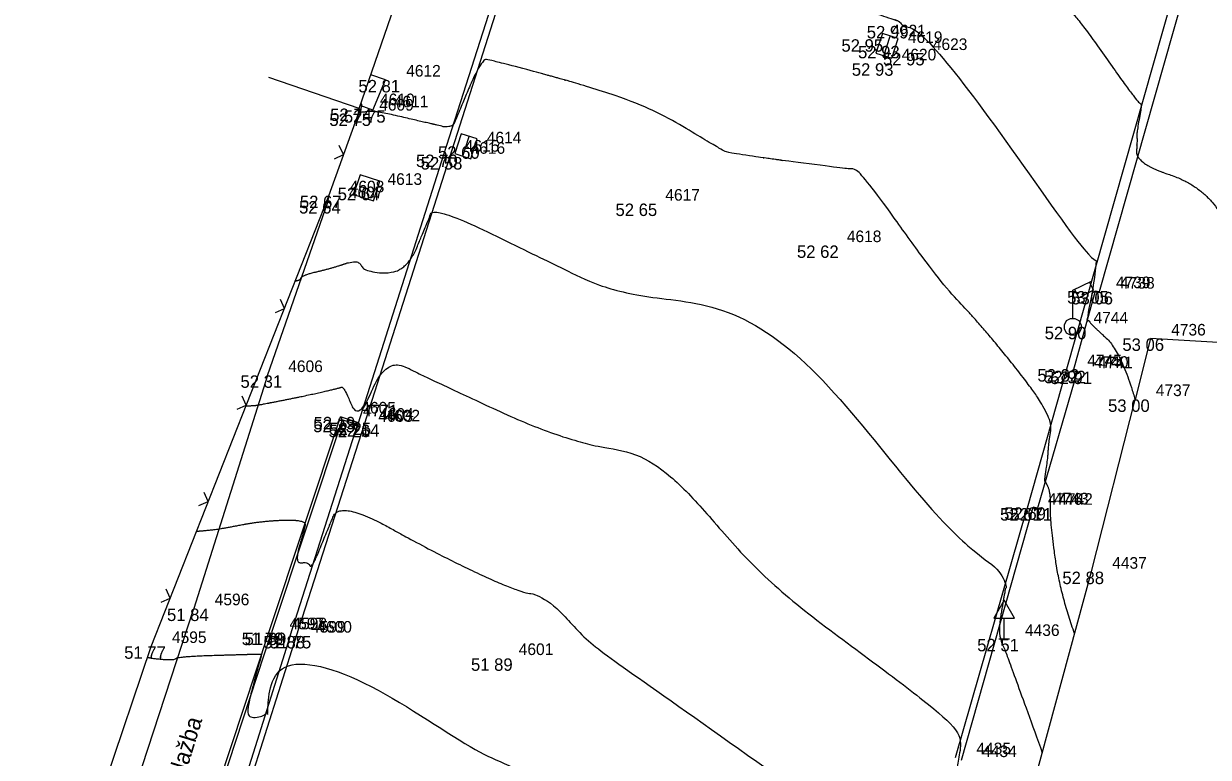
# Model space of a CAD drawing. Extents: x -704017 to -701500, y -1008977 to -1008450.
# Drawn here: x -701728.02 to -701699.5, y -1008889.61 to -1008871.93 of the extents above; entities that cross this region are included whole.
import ezdxf

# ---------------------------------------------------------------- set-up
doc = ezdxf.new("R2010")
doc.units = 0
for name, color, linetype in [('Z_bet_konstrukce', 7, 'Continuous'), ('Z_body', 7, 'Continuous'), ('Z_body_cisla', 7, 'Continuous'), ('Z_body_vysky', 7, 'Continuous'), ('Z_budovy', 7, 'Continuous'), ('Z_chodnik', 7, 'Continuous'), ('Z_dopravni_znaceni', 7, 'Continuous'), ('Z_komunikace', 7, 'Continuous'), ('Z_obruby', 7, 'Continuous'), ('Z_oploceni', 7, 'Continuous'), ('Z_popis', 7, 'Continuous'), ('Z_site_znaky_kanalizace', 7, 'Continuous'), ('Z_site_znaky_nerozlisene', 7, 'Continuous'), ('Z_site_znaky_VO', 7, 'Continuous'), ('Z_vrstevnice_hlavni', 7, 'Continuous'), ('Z_vrstevnice_vedlejsi', 7, 'Continuous'), ('Z_vstupy', 7, 'Continuous')]:
    doc.layers.add(name, color=color, linetype=linetype)

# ---------------------------------------------------------------- blocks, each defined once
blk = doc.blocks.new('POINT_DISPLAY')
blk.add_line((0, 0), (0, 0))
blk = doc.blocks.new('Z212')
for p, q in [((-0.17, 0.17), (0, 0)), ((0, 0), (0.17, 0.17))]:
    blk.add_line(p, q)
blk = doc.blocks.new('Z13')
for p, q in [((0, 0.88), (0.45, 1.1)), ((0, 0.2), (0, 0.88)), ((0.15, 0.7), (0.05, 0.9)), ((0.5, 0.88), (0.15, 0.7)), ((0.4, 1.07), (0.5, 0.88)), ((-0.2, 0.05), (-0.15, 0.15)), ((-0.2, -0.05), (-0.2, 0.05)), ((-0.15, 0.15), (-0.05, 0.2)), ((-0.05, 0.2), (0.05, 0.2)), ((0.05, 0.2), (0.15, 0.15)), ((0.15, 0.15), (0.2, 0.05)), ((0.2, 0.05), (0.2, -0.05)), ((-0.15, -0.15), (-0.2, -0.05)), ((-0.05, -0.2), (-0.15, -0.15)), ((0.05, -0.2), (-0.05, -0.2)), ((0.15, -0.15), (0.05, -0.2)), ((0.2, -0.05), (0.15, -0.15))]:
    blk.add_line(p, q)
blk = doc.blocks.new('Z527')
for p, q in [((0, 0.93), (-0.25, 0.5)), ((0.25, 0.5), (0, 0.93)), ((-0.25, 0.5), (0.25, 0.5)), ((0, 0), (0, 0.5)), ((-0.13, 0), (0.13, 0))]:
    blk.add_line(p, q)
blk = doc.blocks.new('Z38')
for p, q in [((0.25, 0.2), (-0.25, 0.2)), ((-0.25, 0.2), (-0.25, -0.2)), ((-0.25, 0), (0.25, 0)), ((0.25, -0.2), (0.25, 0.2)), ((-0.25, -0.2), (0.25, -0.2))]:
    blk.add_line(p, q)
blk = doc.blocks.new('Z608')
for p, q in [((0.25, 0.25), (-0.25, 0.25)), ((-0.25, 0.25), (-0.25, -0.25)), ((0.25, -0.25), (0.25, 0.25)), ((-0.25, -0.25), (0.25, -0.25))]:
    blk.add_line(p, q)

msp = doc.modelspace()

# ---------------------------------------------------------------- linework, layer by layer
at = {"layer": 'Z_bet_konstrukce'}
for p, q in [((-701719.31, -1008873.29), (-701719.66, -1008873.17)), ((-701719.61, -1008874.02), (-701719.31, -1008873.29)), ((-701719.61, -1008874.02), (-701719.92, -1008873.91))]:
    msp.add_line(p, q, dxfattribs=at)
at = {"layer": 'Z_budovy'}
for p, q in [((-701719.94, -1008873.98), (-701718.32, -1008869.25)), ((-701719.94, -1008873.98), (-701722.12, -1008873.23)), ((-701700.89, -1008879.52), (-701701.26, -1008880.99)), ((-701698.79, -1008879.65), (-701700.89, -1008879.52)), ((-701704.24, -1008892.26), (-701702.31, -1008885.14))]:
    msp.add_line(p, q, dxfattribs=at)
at = {"layer": 'Z_chodnik'}
for p, q in [((-701720.69, -1008876.21), (-701720.67, -1008876.08)), ((-701722.15, -1008880.41), (-701720.69, -1008876.21)), ((-701722.15, -1008880.41), (-701723.92, -1008886.03)), ((-701722.12, -1008886.61), (-701720.39, -1008881.41)), ((-701719.96, -1008881.55), (-701720.39, -1008881.41)), ((-701726.77, -1008894.73), (-701723.92, -1008886.03)), ((-701725.43, -1008896.65), (-701722.12, -1008886.61))]:
    msp.add_line(p, q, dxfattribs=at)
at = {"layer": 'Z_komunikace'}
for p, q in [((-701717.76, -1008875.15), (-701713.25, -1008861.01)), ((-701700.24, -1008870.85), (-701702.91, -1008880.26)), ((-701719.81, -1008881.59), (-701717.76, -1008875.15)), ((-701702.91, -1008880.26), (-701703.86, -1008883.61)), ((-701721.45, -1008886.69), (-701719.81, -1008881.59)), ((-701705.58, -1008889.62), (-701703.86, -1008883.61)), ((-701724.69, -1008896.86), (-701721.45, -1008886.69))]:
    msp.add_line(p, q, dxfattribs=at)
at = {"layer": 'Z_obruby'}
for p, q in [((-701717.9, -1008875.09), (-701713.07, -1008859.91)), ((-701700, -1008870.9), (-701702.12, -1008878.4)), ((-701719.96, -1008881.55), (-701717.9, -1008875.09)), ((-701702.22, -1008878.38), (-701702.75, -1008880.3)), ((-701702.12, -1008878.4), (-701702.22, -1008878.38)), ((-701702.65, -1008880.32), (-701703.61, -1008883.61)), ((-701702.75, -1008880.3), (-701702.65, -1008880.32)), ((-701720.35, -1008881.48), (-701722.05, -1008886.61)), ((-701719.98, -1008881.6), (-701720.35, -1008881.48)), ((-701721.6, -1008886.69), (-701719.98, -1008881.6)), ((-701719.98, -1008881.6), (-701719.96, -1008881.55)), ((-701705.44, -1008889.68), (-701703.71, -1008883.59)), ((-701703.61, -1008883.61), (-701703.71, -1008883.59)), ((-701725.35, -1008896.63), (-701722.05, -1008886.61)), ((-701721.6, -1008886.69), (-701724.81, -1008896.8))]:
    msp.add_line(p, q, dxfattribs=at)
at = {"layer": 'Z_oploceni'}
for p, q in [((-701720.67, -1008876.08), (-701719.96, -1008874.1)), ((-701719.96, -1008874.1), (-701719.94, -1008873.98)), ((-701724.95, -1008886.94), (-701720.67, -1008876.08)), ((-701728.02, -1008896.03), (-701724.95, -1008886.94))]:
    msp.add_line(p, q, dxfattribs=at)
at = {"layer": 'Z_vrstevnice_hlavni'}
for points in [[(-701718.86, -1008870.827), (-701718.722, -1008870.891), (-701718.66, -1008870.875), (-701718.15, -1008870.99), (-701717.866, -1008871.139), (-701716.583, -1008870.95), (-701716.35, -1008870.397), (-701715.903, -1008869.328), (-701715.722, -1008869.338), (-701708.062, -1008871.441), (-701707.666, -1008871.622), (-701707.036, -1008871.849), (-701706.979, -1008871.856), (-701706.917, -1008871.902), (-701706.873, -1008871.965), (-701705.991, -1008872.461), (-701702.302, -1008877.715), (-701702.147, -1008877.571), (-701702.37, -1008878.789), (-701702.424, -1008879.118), (-701702.374, -1008879.073), (-701702.332, -1008879.168), (-701701.594, -1008879.84), (-701701.26, -1008880.99)], [(-701723.856, -1008884.165), (-701723.757, -1008884.159), (-701723.317, -1008884.117), (-701722.306, -1008883.918), (-701721.212, -1008883.88), (-701721.275, -1008884.162), (-701721.5, -1008884.95), (-701721.171, -1008884.904), (-701721.088, -1008885.083), (-701720.729, -1008884.195), (-701720.399, -1008883.421), (-701718.012, -1008884.748), (-701716.089, -1008885.644), (-701715.41, -1008885.731), (-701714.654, -1008886.677), (-701712.69, -1008888.078), (-701706.725, -1008892.293), (-701706.411, -1008892.551), (-701706.575, -1008893.458), (-701706.696, -1008894.086), (-701705.776, -1008894.749), (-701705.243, -1008895.044), (-701705.017, -1008895.187)]]:
    msp.add_open_spline(points, degree=2, dxfattribs=at)
at = {"layer": 'Z_vrstevnice_vedlejsi'}
for points in [[(-701717.871, -1008867.857), (-701717.756, -1008867.838), (-701717.673, -1008867.822), (-701715.485, -1008867.5), (-701715.058, -1008866.486), (-701714.798, -1008865.862), (-701714.692, -1008865.868), (-701710.224, -1008867.095), (-701707.844, -1008868.181), (-701707.424, -1008868.333), (-701705.961, -1008868.506), (-701704.335, -1008869.709), (-701703.188, -1008871.346), (-701702.796, -1008871.566), (-701701.156, -1008873.901), (-701701.088, -1008873.837), (-701701.23, -1008874.615), (-701701.204, -1008874.722), (-701701.244, -1008875.302), (-701699.632, -1008875.838), (-701698.821, -1008877.113), (-701698.653, -1008877.266), (-701698.355, -1008877.477)], [(-701702.715, -1008886.633), (-701703.048, -1008885.709), (-701703.304, -1008883.97), (-701703.286, -1008883.249), (-701703.418, -1008882.952), (-701703.446, -1008882.98), (-701703.355, -1008882.392), (-701703.341, -1008882.053), (-701703.227, -1008881.377), (-701704.937, -1008879.217), (-701705.942, -1008878.19), (-701707.885, -1008875.452), (-701708.146, -1008875.439), (-701711.038, -1008875.063), (-701711.257, -1008874.95), (-701713.196, -1008873.784), (-701716.752, -1008872.808), (-701717.008, -1008872.793), (-701717.642, -1008874.308), (-701717.68, -1008874.4), (-701717.894, -1008874.432), (-701717.942, -1008874.407), (-701718.541, -1008874.272), (-701719.61, -1008874.02), (-701719.96, -1008874.1), (-701719.85, -1008873.881), (-701719.898, -1008873.859)], [(-701721.478, -1008878.131), (-701721.369, -1008878.125), (-701721.309, -1008877.992), (-701720.597, -1008877.828), (-701719.956, -1008877.607), (-701719.832, -1008877.922), (-701718.816, -1008877.961), (-701718.293, -1008876.702), (-701718.133, -1008876.321), (-701715.052, -1008877.835), (-701713.767, -1008878.433), (-701709.999, -1008878.916), (-701705.806, -1008884.163), (-701704.321, -1008885.222), (-701704.421, -1008885.764), (-701704.553, -1008886.557), (-701704.459, -1008886.899), (-701704.403, -1008886.98), (-701703.493, -1008889.504)], [(-701722.667, -1008881.148), (-701722.461, -1008881.136), (-701722.376, -1008881.127), (-701721.27, -1008880.91), (-701720.43, -1008880.717), (-701720.306, -1008880.674), (-701719.96, -1008881.55), (-701719.298, -1008879.98), (-701718.356, -1008880.443), (-701714.928, -1008882.038), (-701712.704, -1008882.323), (-701710.23, -1008885.42), (-701705.37, -1008888.887), (-701705.51, -1008889.65), (-701705.629, -1008890.31), (-701705.649, -1008890.414), (-701705.452, -1008890.557), (-701705.232, -1008890.611), (-701704.313, -1008892.242), (-701704.798, -1008892.26), (-701704.848, -1008892.438), (-701705.159, -1008894.062), (-701704.751, -1008894.196)], [(-701719.96, -1008881.55), (-701720.103, -1008881.56), (-701720.023, -1008881.734), (-701720.009, -1008881.7), (-701719.966, -1008881.599), (-701719.96, -1008881.55)], [(-701725.036, -1008887.196), (-701725.026, -1008887.22), (-701724.401, -1008887.279), (-701724.297, -1008887.181), (-701722.415, -1008887.126), (-701722.29, -1008887.125), (-701722.307, -1008887.191), (-701722.635, -1008888.386), (-701722.61, -1008888.678), (-701722.214, -1008888.623), (-701722.136, -1008888.453), (-701721.45, -1008886.69), (-701717.332, -1008889.472), (-701716.446, -1008889.52), (-701708.776, -1008894.971), (-701707.768, -1008895.954), (-701707.45, -1008896.215), (-701707.521, -1008896.607), (-701707.743, -1008897.758), (-701707.499, -1008897.934), (-701707.358, -1008898.012), (-701706.001, -1008898.87)]]:
    msp.add_open_spline(points, degree=2, dxfattribs=at)
at = {"layer": 'Z_vstupy'}
msp.add_line((-701702.31, -1008885.14), (-701701.26, -1008880.99), dxfattribs=at)

# ---------------------------------------------------------------- block references
at = {"layer": 'Z_body'}
for p in [(-701707.02, -1008871.99), (-701707.63, -1008872.31), (-701707.23, -1008872.47), (-701706.63, -1008872.64), (-701707.38, -1008872.89), (-701719.31, -1008873.29), (-701719.96, -1008874.1), (-701719.94, -1008873.98), (-701719.61, -1008874.02), (-701717.37, -1008874.89), (-701717.9, -1008875.09), (-701717.76, -1008875.15), (-701720.67, -1008876.08), (-701719.76, -1008875.89), (-701720.69, -1008876.21), (-701713.07, -1008876.27), (-701708.7, -1008877.28), (-701702.22, -1008878.38), (-701702.12, -1008878.4), (-701702.76, -1008879.24), (-701700.89, -1008879.52), (-701702.91, -1008880.26), (-701702.75, -1008880.3), (-701702.65, -1008880.32), (-701722.15, -1008880.41), (-701701.26, -1008880.99), (-701720.39, -1008881.41), (-701720.35, -1008881.48), (-701719.98, -1008881.6), (-701719.96, -1008881.55), (-701719.81, -1008881.59), (-701703.86, -1008883.61), (-701703.71, -1008883.59), (-701703.61, -1008883.61), (-701702.31, -1008885.14), (-701723.92, -1008886.03), (-701722.12, -1008886.61), (-701722.05, -1008886.61), (-701724.95, -1008886.94), (-701721.6, -1008886.69), (-701721.45, -1008886.69), (-701704.41, -1008886.76), (-701716.6, -1008887.23)]:
    msp.add_blockref('POINT_DISPLAY', p, dxfattribs=at)
at = {"layer": 'Z_dopravni_znaceni'}
msp.add_blockref('Z527', (-701704.41, -1008886.76), dxfattribs=at)
at = {"layer": 'Z_oploceni'}
for p, rotation in [((-701720.32, -1008875.09), 70.3), ((-701721.74, -1008878.8), 68.5), ((-701722.66, -1008881.13), 68.5), ((-701723.58, -1008883.45), 68.5), ((-701724.49, -1008885.78), 68.5)]:
    msp.add_blockref('Z212', p, dxfattribs=dict(at, rotation=rotation))
at = {"layer": 'Z_site_znaky_kanalizace', "rotation": 72}
for p in [(-701707.23, -1008872.47), (-701717.37, -1008874.89)]:
    msp.add_blockref('Z38', p, dxfattribs=at)
at = {"layer": 'Z_site_znaky_nerozlisene', "rotation": -18.000000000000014}
msp.add_blockref('Z608', (-701719.76, -1008875.89), dxfattribs=at)
at = {"layer": 'Z_site_znaky_VO'}
msp.add_blockref('Z13', (-701702.76, -1008879.24), dxfattribs=at)

# ---------------------------------------------------------------- texts
at = {"layer": 'Z_body_cisla'}
for s, p in [('4621', (-701707.13, -1008872.24)), ('4619', (-701706.73, -1008872.4)), ('4623', (-701706.13, -1008872.57)), ('4620', (-701706.88, -1008872.82)), ('4612', (-701718.81, -1008873.21)), ('4609', (-701719.46, -1008874.03)), ('4610', (-701719.44, -1008873.9)), ('4611', (-701719.11, -1008873.95)), ('4614', (-701716.87, -1008874.82)), ('4615', (-701717.4, -1008875.02)), ('4616', (-701717.26, -1008875.07)), ('4613', (-701719.26, -1008875.82)), ('4608', (-701720.17, -1008876)), ('4607', (-701720.19, -1008876.14)), ('4617', (-701712.57, -1008876.2)), ('4618', (-701708.2, -1008877.2)), ('4739', (-701701.72, -1008878.31)), ('4738', (-701701.62, -1008878.32)), ('4744', (-701702.26, -1008879.16)), ('4736', (-701700.39, -1008879.45)), ('4606', (-701721.65, -1008880.33)), ('4745', (-701702.41, -1008880.19)), ('4740', (-701702.25, -1008880.23)), ('4741', (-701702.15, -1008880.24)), ('4737', (-701700.76, -1008880.91)), ('4605', (-701719.89, -1008881.33)), ('4771', (-701719.85, -1008881.4)), ('4603', (-701719.48, -1008881.53)), ('4604', (-701719.46, -1008881.48)), ('4602', (-701719.31, -1008881.52)), ('4746', (-701703.36, -1008883.53)), ('4743', (-701703.21, -1008883.52)), ('4742', (-701703.11, -1008883.53)), ('4437', (-701701.81, -1008885.07)), ('4596', (-701723.42, -1008885.95)), ('4597', (-701721.62, -1008886.53)), ('4598', (-701721.55, -1008886.53)), ('4599', (-701721.1, -1008886.61)), ('4600', (-701720.95, -1008886.61)), ('4595', (-701724.45, -1008886.86)), ('4436', (-701703.91, -1008886.69)), ('4601', (-701716.1, -1008887.15)), ('4435', (-701705.08, -1008889.54)), ('4434', (-701704.94, -1008889.61))]:
    msp.add_text(s, height=0.28, dxfattribs=at).set_placement(p)
at = {"layer": 'Z_body_vysky'}
for s, p in [('52 99', (-701707.72, -1008872.29)), ('52 95', (-701708.33, -1008872.61)), ('52 93', (-701707.93, -1008872.77)), ('52 95', (-701707.33, -1008872.94)), ('52 93', (-701708.08, -1008873.19)), ('52 81', (-701719.96, -1008873.59)), ('52 75', (-701720.66, -1008874.4)), ('52 74', (-701720.64, -1008874.28)), ('52 75', (-701720.31, -1008874.32)), ('52 60', (-701718.045, -1008875.19)), ('52 70', (-701718.575, -1008875.39)), ('52 58', (-701718.46, -1008875.45)), ('52 67', (-701721.37, -1008876.38)), ('52 64', (-701720.46, -1008876.19)), ('52 64', (-701721.39, -1008876.51)), ('52 65', (-701713.77, -1008876.57)), ('52 62', (-701709.4, -1008877.58)), ('53 05', (-701702.895, -1008878.68)), ('53 06', (-701702.795, -1008878.7)), ('52 90', (-701703.435, -1008879.54)), ('53 06', (-701701.565, -1008879.82)), ('52 82', (-701703.61, -1008880.56)), ('52 92', (-701703.45, -1008880.6)), ('52 91', (-701703.3, -1008880.62)), ('52 31', (-701722.8, -1008880.71)), ('53 00', (-701701.91, -1008881.29)), ('52 23', (-701721.05, -1008881.78)), ('52 19', (-701721.04, -1008881.71)), ('52 26', (-701720.68, -1008881.9)), ('52 25', (-701720.66, -1008881.85)), ('52 14', (-701720.46, -1008881.89)), ('52 61', (-701704.51, -1008883.91)), ('52 69', (-701704.41, -1008883.89)), ('52 71', (-701704.26, -1008883.91)), ('52 88', (-701703.01, -1008885.44)), ('51 84', (-701724.57, -1008886.33)), ('51 79', (-701722.77, -1008886.91)), ('51 89', (-701722.7, -1008886.91)), ('51 77', (-701725.6, -1008887.24)), ('51 88', (-701722.25, -1008886.99)), ('51 75', (-701722.1, -1008886.99)), ('52 51', (-701705.06, -1008887.06)), ('51 89', (-701717.25, -1008887.53))]:
    msp.add_text(s, height=0.3, dxfattribs=at).set_placement(p)
at = {"layer": 'Z_popis'}
msp.add_text('chodník - dlažba', height=0.4, rotation=72.9, dxfattribs=at).set_placement((-701724.87, -1008892.46))

doc.saveas('drawing.dxf')
